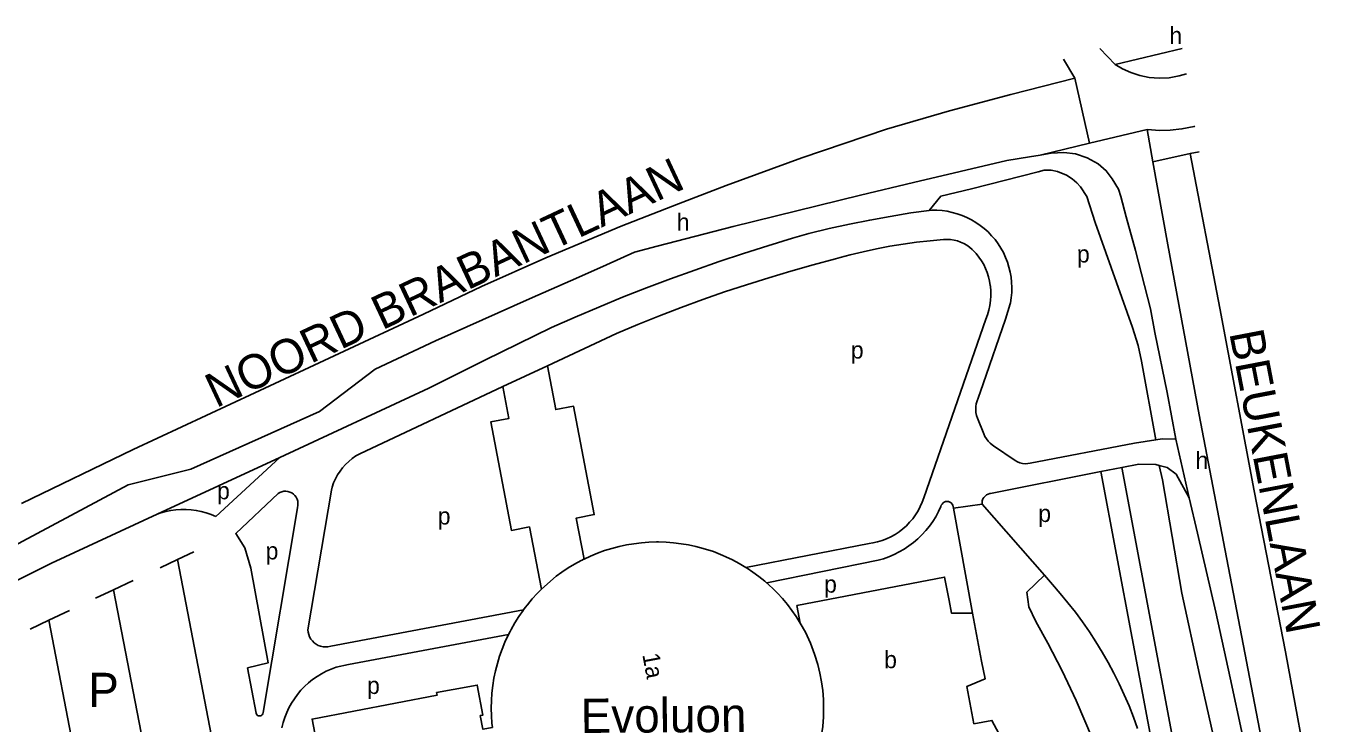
# Model space of a CAD drawing. Extents: x 157569 to 159501, y 382907 to 384670.
# Drawn here: x 159000.4 to 159304.5, y 383822.5 to 383985.3 of the extents above; entities that cross this region are included whole.
import ezdxf

# ---------------------------------------------------------------- set-up
doc = ezdxf.new("R2010")
doc.units = 0
for name, color, linetype in [('BLT_Basislijn', 7, 'Continuous'), ('BLT_Bebouwing', 7, 'Continuous'), ('BLT_Bebouwing_beschrifting', 7, 'Continuous'), ('BLT_Centroide', 7, 'Continuous'), ('BLT_Huisnummer', 7, 'Continuous'), ('BLT_Onderverdeling_panden', 7, 'Continuous'), ('BLT_Straatnaam_hoofdweg', 7, 'Continuous'), ('BLT_Tekst_parkeren', 7, 'Continuous'), ('BLT_Vlakafsluiter', 7, 'Continuous')]:
    doc.layers.add(name, color=color, linetype=linetype)

msp = doc.modelspace()

# ---------------------------------------------------------------- linework, layer by layer
at = {"layer": 'BLT_Basislijn'}
for p, q in [((159254.43, 383976.34), (159270.08, 383980.05)), ((159261.87, 383961.12), (159263.21, 383953.64)), ((159263.21, 383953.64), (159271.94, 383955.52)), ((159271.94, 383955.52), (159274.03, 383955.97)), ((159263.21, 383953.64), (159266.69, 383934.21)), ((159224.29, 383916.89), (159209.78, 383875.26)), ((159107.41, 383907.31), (159122.94, 383914.99)), ((159122, 383906.05), (159138.11, 383913.6)), ((159094.35, 383900.85), (159107.41, 383907.31)), ((159111.62, 383901.19), (159122, 383906.05)), ((159059.59, 383884.64), (159094.35, 383900.85)), ((159078.2, 383885.54), (159111.62, 383901.19)), ((159223.66, 383901.86), (159222.47, 383898.5)), ((159222.28, 383893.85), (159223.79, 383890.15)), ((159226.05, 383887.38), (159231.08, 383883.93)), ((159234.6, 383883.3), (159258.94, 383888)), ((159059.59, 383884.64), (159030.93, 383871.46)), ((159044.62, 383870.91), (159059.59, 383884.64)), ((159256, 383882.32), (159251.1, 383881.35)), ((159259.98, 383883.11), (159256, 383882.32)), ((159251.1, 383881.35), (159225.37, 383876.27)), ((159071.59, 383877.04), (159066.12, 383844.49)), ((159006.3, 383859.97), (159030.93, 383871.46)), ((159055.71, 383825.17), (159063.67, 383872.91)), ((159216.7, 383872.83), (159221.14, 383848.33)), ((159197.05, 383864.6), (159168.25, 383859.03)), ((159035.67, 383860.85), (159039.49, 383862.66)), ((159006.3, 383859.97), (158984.59, 383849.15)), ((159031.64, 383858.94), (159035.67, 383860.85)), ((159045.99, 383807.35), (159035.67, 383860.85)), ((159199.18, 383860.69), (159173.15, 383855.4)), ((159020.77, 383853.81), (159025.38, 383855.99)), ((159237.93, 383857.17), (159233.8, 383853.23)), ((159016.6, 383851.84), (159020.77, 383853.81)), ((159030.32, 383804.32), (159020.77, 383853.81)), ((159005.71, 383846.69), (159010.53, 383848.97)), ((159071.46, 383840.64), (159116.43, 383849.15)), ((159001.37, 383844.64), (159005.71, 383846.69)), ((159014.48, 383801.27), (159005.71, 383846.69))]:
    msp.add_line(p, q, dxfattribs=at)
for points in [[(159254.43, 383976.34), (159256.17, 383975.3), (159258.1, 383974.42), (159260.18, 383973.74), (159262.39, 383973.3), (159264.69, 383973.12), (159267.03, 383973.23), (159269.35, 383973.63), (159271.05, 383974.15)], [(159093.05, 383918.06), (159106.64, 383924.56), (159121.62, 383931.22), (159139.22, 383938.6), (159152.54, 383943.83), (159163.72, 383948.12), (159181.32, 383954.54), (159201.06, 383961.21), (159215.81, 383965.49), (159230.08, 383969.3), (159245.06, 383973.1)], [(159261.87, 383961.12), (159264.88, 383960.89), (159267.29, 383960.97), (159270.01, 383961.27), (159272.87, 383961.87), (159273.05, 383961.93)], [(159236.96, 383955.19), (159234.42, 383954.75), (159229.19, 383953.94), (159207.4, 383948.79), (159195, 383945.81), (159165.33, 383938.56), (159147.56, 383933.9)], [(159268.55, 383888.93), (159266.54, 383899.8), (159263.72, 383913.78), (159262.68, 383919.34), (159259.14, 383932.92), (159256.96, 383940.81), (159255.76, 383945.49), (159255.19, 383947.26), (159253.74, 383949.67), (159252.37, 383951.53), (159250.44, 383953.14), (159247.87, 383954.51), (159245.21, 383955.47), (159242.47, 383955.8), (159239.49, 383955.64), (159236.96, 383955.19)], [(159271.94, 383955.52), (159278.86, 383919.49), (159286.83, 383876.85), (159294.15, 383839.29), (159300.49, 383805.13), (159304.53, 383784.63)], [(159211.07, 383942.27), (159213.73, 383945.56), (159220.9, 383947.28), (159236.44, 383951.24), (159237.86, 383951.62), (159239.5, 383951.62), (159241, 383951.32), (159243.09, 383950.49), (159244.43, 383949.67), (159245.48, 383948.7), (159246.38, 383947.8), (159247.8, 383945.49), (159249.79, 383939.45), (159258.45, 383914.93), (159259.79, 383910.8), (159260.61, 383907.14), (159263.92, 383888.78)], [(159183.01, 383936.91), (159187.72, 383938.02), (159192.46, 383939.05), (159197.2, 383940), (159201.96, 383940.87), (159206.74, 383941.67), (159211.07, 383942.27)], [(159211.07, 383942.27), (159211.67, 383942.31), (159212.87, 383942.3), (159214.07, 383942.22), (159215.26, 383942.06), (159216.44, 383941.82), (159217.6, 383941.49), (159218.74, 383941.1), (159219.85, 383940.63), (159220.92, 383940.08), (159221.96, 383939.47), (159222.95, 383938.79), (159223.89, 383938.05), (159224.79, 383937.24), (159225.62, 383936.37), (159226.4, 383935.46), (159227.12, 383934.49), (159227.77, 383933.48), (159228.35, 383932.42), (159228.86, 383931.33), (159229.3, 383930.21), (159229.66, 383929.06), (159229.94, 383927.89), (159230.15, 383926.71), (159230.27, 383925.51), (159230.32, 383924.31), (159230.29, 383923.1), (159230.18, 383921.91), (159229.98, 383920.72), (159229.94, 383920.52)], [(159122.94, 383914.99), (159128.43, 383917.4), (159133.96, 383919.74), (159139.51, 383922.01), (159145.1, 383924.21), (159150.71, 383926.33), (159156.35, 383928.37), (159162.02, 383930.34), (159167.71, 383932.23), (159173.43, 383934.05), (159179.17, 383935.79), (159183.01, 383936.91)], [(159147.56, 383933.9), (159142.27, 383932.51), (159135.75, 383929.61), (159129.31, 383926.71), (159117.79, 383921.64), (159095.89, 383911.82)], [(159214.41, 383935.47), (159211.26, 383935.19), (159208.12, 383934.84), (159204.99, 383934.41), (159201.87, 383933.9), (159198.77, 383933.32), (159195.68, 383932.65), (159192.61, 383931.9), (159190.32, 383931.3)], [(159214.41, 383935.47), (159215.22, 383935.51), (159216.03, 383935.48), (159216.84, 383935.36), (159217.62, 383935.17), (159218.39, 383934.9), (159219.13, 383934.56), (159219.82, 383934.15), (159220.48, 383933.67), (159221.08, 383933.13), (159221.27, 383932.94)], [(159266.69, 383934.21), (159274, 383894.61), (159279.69, 383864.96), (159290.42, 383809.2), (159295.3, 383784.53), (159298.39, 383770.2), (159301.16, 383757.66)], [(159138.11, 383913.6), (159143.1, 383915.68), (159148.11, 383917.69), (159153.16, 383919.61), (159158.23, 383921.47), (159163.33, 383923.25), (159168.46, 383924.95), (159173.61, 383926.58), (159178.78, 383928.13), (159183.98, 383929.61), (159189.19, 383931), (159190.32, 383931.3)], [(159221.27, 383932.94), (159221.99, 383932.2), (159222.64, 383931.4), (159223.24, 383930.55), (159223.77, 383929.67), (159224.22, 383928.74), (159224.61, 383927.78), (159224.91, 383926.8), (159225.15, 383925.79), (159225.3, 383924.77), (159225.32, 383924.58)], [(159225.32, 383924.58), (159225.41, 383923.47), (159225.42, 383922.35), (159225.35, 383921.23), (159225.21, 383920.12), (159224.98, 383919.02), (159224.67, 383917.95), (159224.29, 383916.89)], [(159229.94, 383920.52), (159228.84, 383916.94), (159223.66, 383901.86)], [(158999.28, 383873.91), (159025.35, 383886.49), (159053.71, 383899.76), (159093.05, 383918.06)], [(158964.93, 383846.79), (158971.61, 383850.8), (158992.88, 383861.55), (159024.21, 383878.25), (159038.85, 383881.91), (159068.81, 383895.41), (159081.84, 383905.25), (159095.89, 383911.82)], [(159122, 383906.05), (159123.93, 383895.82), (159128.09, 383896.61), (159132.92, 383871.33), (159128.71, 383870.53), (159130.53, 383860.95)], [(159111.62, 383901.19), (159113, 383893.76), (159108.8, 383892.99), (159113.61, 383867.66), (159117.8, 383868.45), (159120.62, 383853.91)], [(159222.47, 383898.5), (159222.21, 383897.86), (159222.03, 383897.19), (159221.93, 383896.51), (159221.9, 383895.82), (159221.96, 383895.13), (159222.09, 383894.45), (159222.28, 383893.85)], [(159223.79, 383890.15), (159224.05, 383889.55), (159224.38, 383888.98), (159224.78, 383888.46), (159225.24, 383887.99), (159225.75, 383887.58), (159226.05, 383887.38)], [(159258.94, 383888), (159263.92, 383888.78)], [(159263.92, 383888.78), (159265.41, 383889.01), (159268.55, 383888.93)], [(159078.2, 383885.54), (159077.31, 383885.01), (159076.47, 383884.41), (159075.67, 383883.75), (159074.92, 383883.04), (159074.23, 383882.26), (159073.61, 383881.44), (159073.05, 383880.57), (159072.55, 383879.65), (159072.13, 383878.71), (159071.79, 383877.73), (159071.59, 383877.04)], [(159231.08, 383883.93), (159231.62, 383883.63), (159232.2, 383883.41), (159232.81, 383883.27), (159233.43, 383883.2), (159234.05, 383883.22), (159234.6, 383883.3)], [(159256, 383882.32), (159274.29, 383785.01), (159274.59, 383782.62), (159274.58, 383780.28), (159274.11, 383778.08), (159273.77, 383777.12)], [(159264.66, 383882.8), (159263.9, 383883.01), (159259.98, 383883.11)], [(159285.49, 383779.47), (159282.98, 383791.65), (159277.9, 383817.17), (159274.08, 383834.03), (159269.97, 383853.02), (159265.44, 383879.46), (159264.66, 383882.8)], [(159271.66, 383875.22), (159268.68, 383880.75), (159266.56, 383882.3), (159264.66, 383882.8)], [(159251.1, 383881.35), (159269.35, 383784.24), (159269.59, 383782.33), (159269.58, 383780.82), (159269.29, 383779.45), (159268.88, 383778.28), (159266.88, 383774.82)], [(159059.15, 383876.26), (159049.28, 383866.94), (159051.43, 383863.57), (159052.8, 383858.83), (159056.82, 383836.76), (159052.04, 383835.57), (159054.03, 383825.02)], [(159059.15, 383876.26), (159059.57, 383876.51), (159060.02, 383876.68), (159060.5, 383876.78), (159060.99, 383876.8), (159061.47, 383876.74), (159061.93, 383876.6), (159062.37, 383876.38), (159062.77, 383876.1), (159063.11, 383875.76), (159063.4, 383875.36), (159063.61, 383874.93), (159063.75, 383874.46), (159063.81, 383873.98), (159063.8, 383873.49), (159063.7, 383873.02), (159063.67, 383872.91)], [(159223.39, 383873.73), (159223.38, 383874.16), (159223.44, 383874.58), (159223.58, 383874.98), (159223.8, 383875.34), (159224.08, 383875.66), (159224.41, 383875.92), (159224.79, 383876.12), (159225.19, 383876.24), (159225.37, 383876.27)], [(159209.78, 383875.26), (159209.41, 383874.21), (159208.97, 383873.2), (159208.45, 383872.22), (159207.86, 383871.27), (159207.21, 383870.37), (159206.49, 383869.53), (159205.72, 383868.73), (159204.89, 383867.99), (159204.01, 383867.32), (159203.08, 383866.71), (159202.11, 383866.17), (159201.1, 383865.7), (159200.07, 383865.3), (159199, 383864.98), (159197.92, 383864.73), (159197.05, 383864.6)], [(159213.77, 383873.22), (159213.21, 383872.02), (159212.57, 383870.85), (159211.86, 383869.72), (159211.09, 383868.64), (159210.25, 383867.61), (159209.35, 383866.63), (159208.39, 383865.71), (159207.38, 383864.84), (159206.33, 383864.04), (159205.22, 383863.3), (159204.07, 383862.63), (159202.88, 383862.03), (159201.66, 383861.51), (159200.41, 383861.05), (159199.18, 383860.69)], [(159216.7, 383872.83), (159216.68, 383873.18), (159216.58, 383873.51), (159216.41, 383873.8), (159216.18, 383874.05), (159215.89, 383874.24), (159215.57, 383874.36), (159215.22, 383874.4), (159214.88, 383874.36), (159214.56, 383874.24), (159214.27, 383874.05), (159214.04, 383873.8), (159213.86, 383873.51), (159213.77, 383873.22)], [(159223.39, 383873.73), (159216.7, 383872.83)], [(159223.39, 383873.73), (159237.93, 383857.17)], [(159296.44, 383757.89), (159295.44, 383761.42), (159287.79, 383800.1), (159284.11, 383819.93), (159281.29, 383833.29), (159277.89, 383848.59), (159273.64, 383867), (159271.66, 383875.22)], [(159044.62, 383870.91), (159043.52, 383871.38), (159042.4, 383871.77), (159041.24, 383872.09), (159040.07, 383872.32), (159038.89, 383872.48), (159037.7, 383872.56), (159036.5, 383872.56), (159035.31, 383872.48), (159034.13, 383872.32), (159032.96, 383872.08), (159031.81, 383871.76), (159030.93, 383871.46)], [(159237.93, 383857.17), (159239.78, 383855.06), (159241.63, 383852.95), (159243.42, 383850.79), (159245.15, 383848.57), (159246.81, 383846.31), (159248.41, 383844.01), (159249.94, 383841.65), (159251.4, 383839.26), (159252.8, 383836.82), (159254.12, 383834.35), (159255.38, 383831.83), (159256.56, 383829.29), (159257.67, 383826.71), (159258.71, 383824.1), (159259.67, 383821.46)], [(159233.8, 383853.23), (159234.28, 383849.85), (159235.93, 383846.38), (159238.72, 383841.32), (159242.08, 383834.93), (159245.36, 383827.95), (159250.93, 383814.86), (159252.86, 383808.66), (159254.14, 383802.89), (159254.57, 383795.83), (159254.78, 383789.51), (159254.56, 383785.16), (159253.64, 383775.25), (159252.07, 383767.05), (159249.77, 383759.16), (159246.77, 383752.46)], [(159066.12, 383844.49), (159066.18, 383843.92), (159066.32, 383843.36), (159066.53, 383842.82), (159066.82, 383842.32), (159067.17, 383841.87), (159067.58, 383841.46), (159068.04, 383841.12), (159068.55, 383840.84), (159069.09, 383840.64), (159069.65, 383840.51), (159070.23, 383840.47), (159070.8, 383840.5), (159071.46, 383840.64)], [(159072.69, 383835.73), (159075.6, 383836.34), (159112.94, 383843.4)], [(159072.69, 383835.73), (159071.53, 383835.3), (159070.4, 383834.79), (159069.3, 383834.22), (159068.25, 383833.57), (159067.23, 383832.86), (159066.27, 383832.08), (159065.36, 383831.24), (159064.5, 383830.35), (159063.7, 383829.4), (159062.97, 383828.4), (159062.3, 383827.36), (159061.7, 383826.27), (159061.17, 383825.15), (159060.72, 383824), (159060.34, 383822.82), (159060.04, 383821.62)], [(159054.03, 383825.02), (159054.13, 383824.78), (159054.3, 383824.58), (159054.52, 383824.44), (159054.77, 383824.37), (159055.03, 383824.39), (159055.27, 383824.48), (159055.48, 383824.64), (159055.63, 383824.86), (159055.71, 383825.17)], [(159221.47, 383822.52), (159225.67, 383823.32), (159228.31, 383818.43), (159231.1, 383812.06), (159232.44, 383807.83)]]:
    msp.add_lwpolyline(points, dxfattribs=at)
at = {"layer": 'BLT_Bebouwing'}
for p, q in [((159158.29, 383863.46), (159156.63, 383863.9)), ((159130.44, 383860.91), (159130.09, 383860.73)), ((159130.53, 383860.95), (159130.44, 383860.91)), ((159163.64, 383861.5), (159162.9, 383861.83)), ((159130.09, 383860.73), (159129.89, 383860.63)), ((159168.56, 383858.84), (159168.25, 383859.03)), ((159124.07, 383856.94), (159120.62, 383853.91)), ((159172.93, 383855.59), (159172.71, 383855.78)), ((159173.1, 383855.44), (159172.93, 383855.59)), ((159173.15, 383855.4), (159173.1, 383855.44)), ((159120.14, 383853.48), (159119.62, 383852.95)), ((159120.62, 383853.91), (159120.14, 383853.48)), ((159175.04, 383853.64), (159174.8, 383853.88)), ((159116.43, 383849.14), (159116.32, 383849)), ((159116.83, 383849.68), (159116.43, 383849.15)), ((159116.43, 383849.15), (159116.43, 383849.14)), ((159112.94, 383843.4), (159112.52, 383842.55)), ((159113.27, 383844.07), (159112.94, 383843.4)), ((159113.35, 383844.23), (159113.27, 383844.07)), ((159112.25, 383841.97), (159112.09, 383841.6)), ((159112.52, 383842.55), (159112.25, 383841.97))]:
    msp.add_line(p, q, dxfattribs=at)
for points in [[(159147.43, 383864.95), (159145.67, 383864.9), (159143.92, 383864.77), (159142.17, 383864.55), (159140.43, 383864.27), (159138.71, 383863.9), (159137.01, 383863.45), (159135.32, 383862.93), (159133.67, 383862.33), (159132.04, 383861.66), (159130.53, 383860.95)], [(159156.63, 383863.9), (159154.91, 383864.27), (159153.17, 383864.55), (159151.42, 383864.77), (159149.67, 383864.9), (159147.91, 383864.95), (159147.43, 383864.95)], [(159158.29, 383863.46), (159160.76, 383862.69), (159162.9, 383861.83)], [(159166.72, 383859.94), (159165.17, 383860.78), (159163.64, 383861.5)], [(159129.89, 383860.63), (159128.34, 383859.79), (159126.84, 383858.88), (159125.37, 383857.9), (159124.07, 383856.94)], [(159168.25, 383859.03), (159166.74, 383859.93), (159166.72, 383859.94)], [(159172.71, 383855.78), (159171.34, 383856.89), (159169.91, 383857.93), (159168.56, 383858.84)], [(159174.8, 383853.88), (159173.52, 383855.07), (159173.15, 383855.4)], [(159180.19, 383850.13), (159214.64, 383856.77), (159215.68, 383851.31)], [(159119.62, 383852.95), (159118.44, 383851.65), (159117.31, 383850.3), (159116.83, 383849.68)], [(159180.97, 383846.04), (159180.03, 383847.53), (159179.03, 383848.98), (159177.96, 383850.38), (159176.83, 383851.73), (159175.64, 383853.03), (159175.04, 383853.64)], [(159116.32, 383849), (159115.32, 383847.55), (159114.38, 383846.06), (159113.51, 383844.53), (159113.35, 383844.23)], [(159180.97, 383846.04), (159180.19, 383850.13)], [(159216.53, 383848.38), (159216.24, 383848.38), (159215.68, 383851.31)], [(159221.14, 383848.33), (159216.53, 383848.38)], [(159223.28, 383837.16), (159221.14, 383848.33)], [(159112.09, 383841.6), (159111.43, 383839.97), (159110.84, 383838.31), (159110.32, 383836.63), (159109.89, 383834.93), (159109.53, 383833.2), (159109.25, 383831.47), (159109.05, 383829.72), (159108.93, 383827.96), (159108.89, 383826.2), (159108.93, 383824.44), (159109.05, 383822.69), (159109.15, 383821.7)], [(159221.47, 383822.52), (159219.83, 383831.25), (159224.07, 383833.01), (159223.28, 383837.16)], [(159070.97, 383803.16), (159067.08, 383823.65), (159096.26, 383829.2), (159096.13, 383829.81), (159100, 383830.52), (159105.61, 383831.59), (159106.94, 383824.58), (159106.33, 383824.47), (159106.94, 383821.27), (159109.15, 383821.7)]]:
    msp.add_lwpolyline(points, dxfattribs=at)
at = {"layer": 'BLT_Onderverdeling_panden'}
msp.add_lwpolyline([(159185.95, 383819.99), (159186.21, 383821.91), (159186.38, 383824.17), (159186.43, 383826.2), (159186.38, 383828.21), (159186.21, 383830.3), (159185.94, 383832.31), (159185.56, 383834.38), (159185.08, 383836.35), (159184.33, 383838.75), (159183.34, 383841.33), (159182.16, 383843.88), (159180.97, 383846.04)], dxfattribs=at)
at = {"layer": 'BLT_Vlakafsluiter'}
for p, q in [((159250.87, 383980.07), (159254.43, 383976.34)), ((159242.37, 383977.54), (159245.06, 383973.1)), ((159245.06, 383973.1), (159248.45, 383957.93)), ((159248.45, 383957.93), (159261.87, 383961.12)), ((159236.96, 383955.19), (159248.45, 383957.93)), ((159268.55, 383888.93), (159271.66, 383875.22))]:
    msp.add_line(p, q, dxfattribs=at)

# ---------------------------------------------------------------- texts
at = {"layer": 'BLT_Bebouwing_beschrifting'}
msp.add_text('Evoluon', height=8, rotation=0.3387, dxfattribs=at).set_placement((159129.78, 383820.41))
at = {"layer": 'BLT_Centroide'}
for s, p in [('h', (159267.08, 383981.05)), ('h', (159152.17, 383937.54)), ('p', (159245.52, 383930.12)), ('p', (159192.78, 383907.72)), ('h', (159273.18, 383881.99)), ('p', (159044.93, 383874.9)), ('p', (159096.42, 383869.01)), ('p', (159236.49, 383869.61)), ('p', (159056.26, 383860.88)), ('p', (159186.54, 383853.13)), ('b', (159200.55, 383835.51)), ('p', (159079.92, 383829.5))]:
    msp.add_text(s, height=4, dxfattribs=at).set_placement(p)
at = {"layer": 'BLT_Huisnummer'}
msp.add_text('1a', height=4, rotation=280.6261, dxfattribs=at).set_placement((159144.11, 383838.68))
at = {"layer": 'BLT_Straatnaam_hoofdweg'}
for s, rotation, p in [('NOORD BRABANTLAAN', 25.1074, (159044.69, 383896.11)), ('BEUKENLAAN', 280.8521, (159281.02, 383913.73))]:
    msp.add_text(s, height=8, rotation=rotation, dxfattribs=at).set_placement(p)
at = {"layer": 'BLT_Tekst_parkeren'}
msp.add_text('P', height=8, dxfattribs=at).set_placement((159014.88, 383826.44))

doc.saveas('drawing.dxf')
